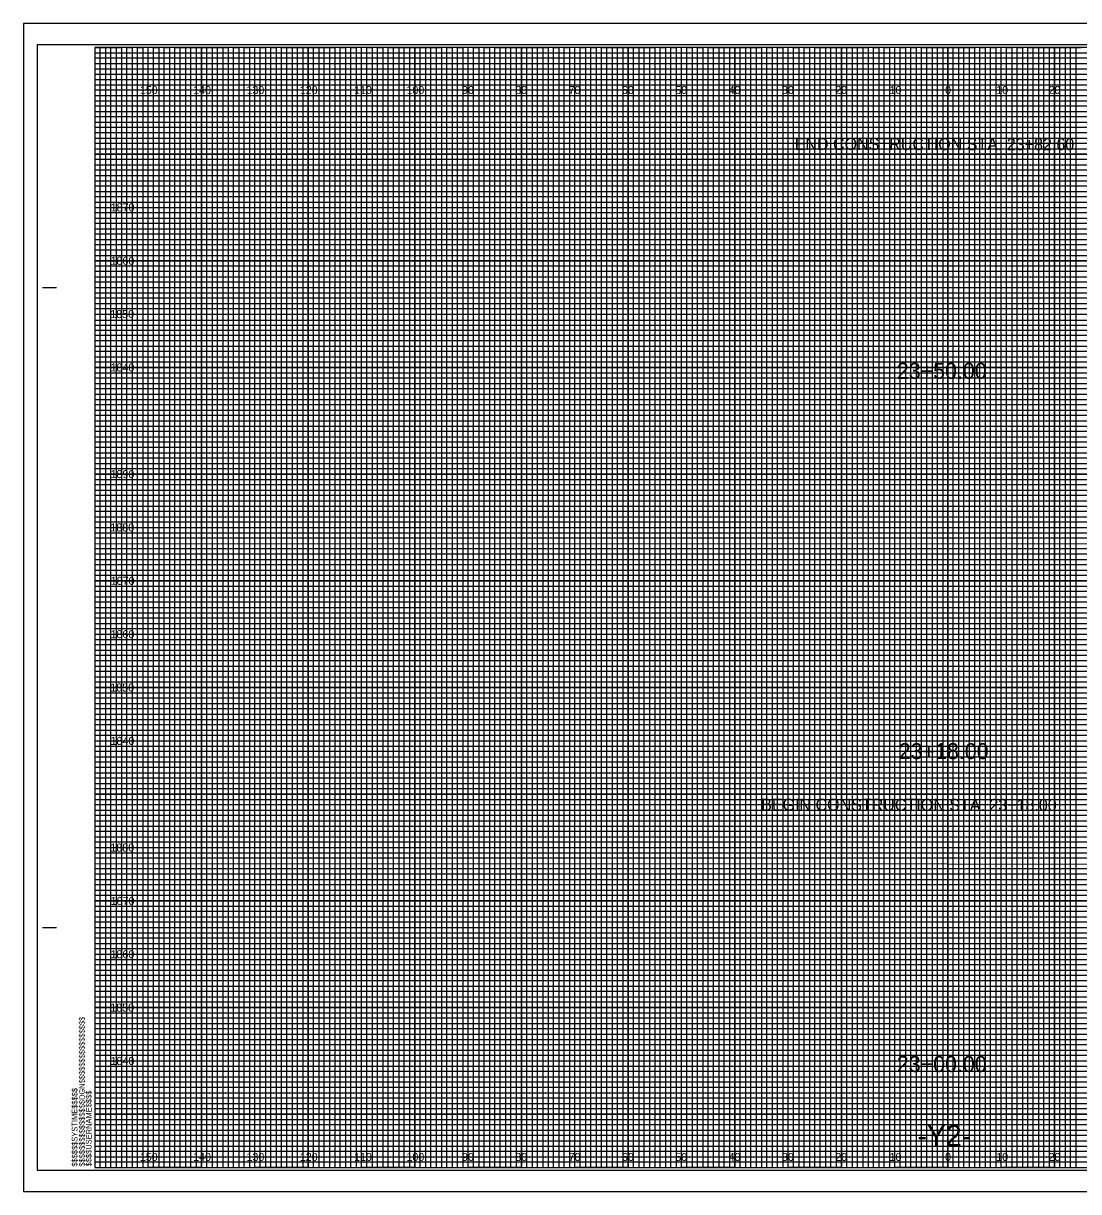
# Model space of a CAD drawing. Extents: x -13 to 323, y -4 to 214.
# Drawn here: x -13.4 to 184.5, y -4.5 to 214.5 of the extents above; entities that cross this region are included whole.
import ezdxf

# ---------------------------------------------------------------- set-up
doc = ezdxf.new("R2010")
doc.units = 0
for name, color, linetype in [('Prop XS Alignment Label', 7, 'Continuous'), ('Prop XS Elevation Labels', 7, 'Continuous'), ('Prop XS Offset Labels', 7, 'Continuous'), ('Prop XS SE Text', 7, 'Continuous'), ('Prop XS Station Labels', 7, 'Continuous'), ('Sheet Cross Section CELL', 7, 'Continuous'), ('Sheet Cross Section Grid Major CELL', 7, 'Continuous'), ('Sheet Cross Section Grid Middle CELL', 7, 'Continuous'), ('Sheet Cross Section Grid Minor 1 CELL', 7, 'Continuous'), ('Sheet Cross Section Grid Minor 2 CELL', 7, 'Continuous'), ('Sheet Cutting Line CELL', 7, 'Continuous'), ('Sheet DOT Grid CELL', 7, 'Continuous'), ('Sheet Plot Border Inside CELL', 7, 'Continuous'), ('Sheet Plot Border Outside CELL', 7, 'Continuous')]:
    doc.layers.add(name, color=color, linetype=linetype)

msp = doc.modelspace()

# ---------------------------------------------------------------- linework, layer by layer
at = {"layer": 'Sheet Cross Section CELL'}
for p, q in [((-9.8, 165), (-7.3, 165)), ((-9.7, 165), (-7.2, 165)), ((-9.8, 45), (-7.3, 45)), ((-9.7, 45), (-7.2, 45))]:
    msp.add_line(p, q, dxfattribs=at)
msp.add_lwpolyline([(320, 210), (0, 210), (0, 0), (320, 0)], close=True, dxfattribs=at)
at = {"layer": 'Sheet Cross Section Grid Major CELL'}
for p, q in [((10, 210), (0, 210)), ((10, 0), (10, 210)), ((30, 210), (20, 210)), ((20, 210), (20, 0)), ((30, 0), (30, 210)), ((50, 210), (40, 210)), ((40, 210), (40, 0)), ((50, 0), (50, 210)), ((70, 210), (60, 210)), ((60, 210), (60, 0)), ((70, 0), (70, 210)), ((90, 210), (80, 210)), ((80, 210), (80, 0)), ((90, 0), (90, 210)), ((110, 210), (100, 210)), ((100, 210), (100, 0)), ((110, 0), (110, 210)), ((130, 210), (120, 210)), ((120, 210), (120, 0)), ((130, 0), (130, 210)), ((150, 210), (140, 210)), ((140, 210), (140, 0)), ((150, 0), (150, 210)), ((170, 210), (160, 210)), ((160, 210), (160, 0)), ((170, 0), (170, 210)), ((190, 210), (180, 210)), ((180, 210), (180, 0)), ((20, 0), (10, 0)), ((40, 0), (30, 0)), ((60, 0), (50, 0)), ((80, 0), (70, 0)), ((100, 0), (90, 0)), ((120, 0), (110, 0)), ((140, 0), (130, 0)), ((160, 0), (150, 0)), ((180, 0), (170, 0))]:
    msp.add_line(p, q, dxfattribs=at)
for points in [[(0, 200), (320, 200), (320, 190), (0, 190)], [(0, 180), (320, 180), (320, 170), (0, 170)], [(0, 160), (320, 160), (320, 150), (0, 150)], [(0, 140), (320, 140), (320, 130), (0, 130)], [(0, 120), (320, 120), (320, 110), (0, 110)], [(0, 100), (320, 100), (320, 90), (0, 90)], [(0, 80), (320, 80), (320, 70), (0, 70)], [(0, 60), (320, 60), (320, 50), (0, 50)], [(0, 40), (320, 40), (320, 30), (0, 30)], [(0, 20), (320, 20), (320, 10), (0, 10)]]:
    msp.add_lwpolyline(points, dxfattribs=at)
at = {"layer": 'Sheet Cross Section Grid Middle CELL'}
for points in [[(0, 210), (5, 210), (5, 0), (15, 0), (15, 210), (25, 210), (25, 0), (35, 0), (35, 210), (45, 210), (45, 0), (55, 0), (55, 210), (65, 210), (65, 0), (75, 0), (75, 210), (85, 210), (85, 0), (95, 0), (95, 210), (105, 210), (105, 0), (115, 0), (115, 210), (125, 210), (125, 0), (135, 0), (135, 210), (145, 210), (145, 0), (155, 0), (155, 210), (165, 210), (165, 0), (175, 0), (175, 210), (185, 210)], [(0, 205), (275, 205)], [(0, 185), (320, 185), (320, 195), (0, 195)], [(0, 165), (320, 165), (320, 175), (0, 175)], [(0, 145), (320, 145), (320, 155), (0, 155)], [(0, 125), (320, 125), (320, 135), (0, 135)], [(0, 105), (320, 105), (320, 115), (0, 115)], [(0, 85), (320, 85), (320, 95), (0, 95)], [(0, 65), (320, 65), (320, 75), (0, 75)], [(0, 45), (320, 45), (320, 55), (0, 55)], [(0, 25), (320, 25), (320, 35), (0, 35)], [(0, 5), (320, 5), (320, 15), (0, 15)]]:
    msp.add_lwpolyline(points, dxfattribs=at)
at = {"layer": 'Sheet Cross Section Grid Minor 1 CELL'}
for p, q in [((0, 209), (260, 209)), ((260, 207.98), (0, 207.98)), ((0, 207.98), (0, 207)), ((0, 207), (260, 207)), ((260, 205.89), (0, 205.89)), ((0, 205.89), (0, 204)), ((0, 204), (320, 204))]:
    msp.add_line(p, q, dxfattribs=at)
for points in [[(0, 203), (270, 203), (320, 203), (320, 202), (0, 202)], [(0, 201), (320, 201), (320, 199), (0, 199)], [(0, 198), (320, 198), (320, 197), (0, 196.98)], [(0, 196), (320, 196), (320, 194), (0, 194)], [(0, 193), (320, 193), (320, 192), (0, 192)], [(0, 191), (320, 191), (320, 189), (0, 189)], [(0, 188), (320, 188), (320, 187), (0, 187)], [(0, 186), (320, 186), (320, 184), (0, 184)], [(0, 183), (320, 183), (320, 182), (0, 182)], [(0, 181), (320, 181), (320, 179), (0, 179)], [(0, 178), (320, 178), (320, 177), (0, 177)], [(0, 176), (320, 176), (320, 173.95), (320, 173), (320, 172), (0, 172)], [(0, 174), (320, 174), (320, 173), (0, 173)], [(0, 171), (320, 171), (320, 169), (0, 169.03)], [(0, 169.03), (320, 169), (320, 168), (0, 168)], [(0, 167), (320, 167), (320, 166), (0, 166)], [(0, 164), (320, 164), (320, 163), (0, 163)], [(0, 162), (320, 162), (320, 161), (0, 161)], [(-0.07, 158.89), (320, 158.89), (320, 157.88), (-0.07, 157.88)], [(0, 157), (320, 157), (320, 156), (0, 156)], [(0, 154), (320, 154), (320, 153), (0, 153)], [(0, 152), (320, 152), (320, 151), (0, 151)], [(0, 149), (320, 149), (320, 148), (0, 148)], [(0, 147), (320, 147), (320, 146), (0, 146)], [(0, 144), (320, 144), (320, 143), (0, 143)], [(0, 142), (320, 142), (320, 141), (0, 141)], [(0, 139), (320, 139), (319.99, 137.98), (0, 138)], [(0, 137), (320, 137), (320, 136), (0, 136)], [(0, 134), (320, 134), (320, 133), (0, 133)], [(0, 132), (320, 132), (320, 131), (0, 131)], [(0, 129), (320, 129), (320, 128), (0, 128)], [(0, 127), (320, 127), (320, 126), (0, 126)], [(0, 124), (320, 124), (320, 123), (0, 123)], [(0, 122), (320, 122), (320, 121), (0, 121)], [(0, 119), (320, 119), (320, 118), (0, 118)], [(0, 116.99), (320.07, 116.91), (320, 116), (0, 116)], [(0, 114), (320, 114), (320, 113), (0, 113)], [(0, 112), (320, 112), (320, 111), (0, 111)], [(0, 109), (320, 109), (320, 108), (0, 108)], [(0, 107), (320, 107), (320, 106), (0, 106)], [(0, 104), (320, 104), (320, 103), (0, 103)], [(0, 102), (320, 102), (320, 101), (0, 101)], [(0, 99), (320, 99), (320, 98), (0, 98)], [(0, 97), (320, 97), (320, 96), (0, 96)], [(0, 94), (320, 94), (320, 93), (0, 93)], [(0, 92), (320, 92), (320, 91), (0, 91)], [(0, 89), (320, 89), (320, 88), (0, 88)], [(0, 87), (320, 87), (320, 86), (0, 86)], [(0, 84), (320, 84), (320, 83), (0, 83)], [(0, 82), (320, 82), (320, 81), (0, 81)], [(0, 79), (320, 79), (319.99, 77.98), (0, 78)], [(0, 77), (320, 77), (320, 76), (0, 76)], [(0, 74), (320, 74), (320, 73), (0, 73)], [(0, 72), (320, 72), (320, 71), (0, 71)], [(0, 69), (320, 69), (320, 68), (0, 68)], [(0, 67), (320, 67), (320, 66), (0, 66)], [(0, 64), (320, 64), (320, 63), (0, 63)], [(0, 62), (320, 62), (320, 61), (0, 61)], [(0, 59), (320, 59), (320, 58), (0, 58)], [(0, 56.99), (320.07, 56.91), (320, 56), (0, 56)], [(0, 54), (320, 54), (320, 53), (0, 53)], [(0, 52), (320, 52), (320, 51), (0, 51)], [(0, 49), (320, 49), (320, 48), (0, 48)], [(0, 47), (320, 47), (320, 46), (0, 46)], [(0, 44), (320, 44), (320, 43), (0, 43)], [(0, 42), (320, 42), (320, 41), (0, 41)], [(0, 39), (320, 39), (320, 38), (0, 38)], [(0, 37), (320, 37), (320, 36), (0, 36)], [(0, 34), (320, 34), (320, 33), (0, 33)], [(0, 32), (320, 32), (320, 31), (0, 31)], [(0, 29), (320, 29), (320, 28), (0, 28)], [(0, 27), (320, 27), (320, 26), (0, 26)], [(0, 24), (320, 24), (320, 23), (0, 23)], [(0, 22), (320, 22), (320, 21), (0, 21)], [(0, 19), (320, 19), (320, 18), (0, 18)], [(0, 17), (320, 17), (320, 16), (0, 16)], [(0, 14), (320, 14), (320, 13), (0, 13)], [(0, 12), (320, 12), (320, 11), (0, 11)], [(0, 9), (320, 9), (320, 8), (0, 8)], [(0, 7), (320, 7), (320, 6), (0, 6)], [(0, 4), (320, 4), (320, 3), (0, 3)], [(0, 2), (320, 2), (320, 1), (0, 1)]]:
    msp.add_lwpolyline(points, dxfattribs=at)
at = {"layer": 'Sheet Cross Section Grid Minor 2 CELL'}
for points in [[(0, 0), (1, 0), (1, 210), (2, 210), (2, 0)], [(2, 0), (3, 0), (3, 210), (4, 210), (4, 0)], [(5, 0), (6, 0), (6, 210), (7, 210), (7, 0)], [(7, 0), (8, 0), (8, 210), (9, 210), (9, 0)], [(10, 0), (11, 0), (11, 210), (12, 210), (12, 0)], [(12, 0), (13, 0), (13, 210), (14, 210), (14, 0)], [(15, 0), (16, 0), (16, 210), (17, 210), (17, 0)], [(17, 0), (18, 0), (18, 210), (19, 210), (19, 0)], [(20, 0), (21, 0), (21, 210), (22, 210), (22, 0)], [(22, 0), (23, 0), (23, 210), (24, 210), (24, 0)], [(25, 0), (26, 0), (26, 210), (27, 210), (27, 0)], [(27, 0), (28, 0), (28, 210), (29, 210), (29, 0)], [(30, 0), (31, 0), (31, 210), (32, 210), (32, 0)], [(32, 0), (33, 0), (33, 210), (34, 210), (34, 0)], [(35, 0), (36, 0), (36, 210), (37, 210), (37, 0)], [(37, 0), (38, 0), (38, 210), (39, 210), (39, 0)], [(40, 0), (41, 0), (41, 210), (42, 210), (42, 0)], [(42, 0), (43, 0), (43, 210), (44, 210), (44, 0)], [(45, 0), (46, 0), (46, 210), (47, 210), (47, 0)], [(47, 0), (48, 0), (48, 210), (49, 210), (49, 0)], [(50, 0), (51, 0), (51, 210), (52, 210), (52, 0)], [(52, 0), (53, 0), (53, 210), (54, 210), (54, 0)], [(55, 0), (56, 0), (56, 210), (57, 210), (57, 0)], [(57, 0), (58, 0), (58, 210), (59, 210), (59, 0)], [(60, 0), (61, 0), (61, 210), (62, 210), (62, 0)], [(62, 0), (63, 0), (63, 210), (64, 210), (64, 0)], [(65, 0), (66, 0), (66, 210), (67, 210), (67, 0)], [(67, 0), (68, 0), (68, 210), (69, 210), (69, 0)], [(70, 0), (71, 0), (71, 210), (72, 210), (72, 0)], [(72, 0), (73, 0), (73, 210), (74, 210), (74, 0)], [(75, 0), (76, 0), (76, 210), (77, 210), (77, 0)], [(77, 0), (78, 0), (78, 210), (79, 210), (79, 0)], [(80, 0), (81, 0), (81, 210), (82, 210), (82, 0)], [(82, 0), (83, 0), (83, 210), (84, 210), (84, 0)], [(85, 0), (86, 0), (86, 210), (87, 210), (87, 0)], [(87, 0), (88, 0), (88, 210), (89, 210), (89, 0)], [(90, 0), (91, 0), (91, 210), (92, 210), (92, 0)], [(92, 0), (93, 0), (93, 210), (94, 210), (94, 0)], [(95, 0), (96, 0), (96, 210), (97, 210), (97, 0)], [(97, 0), (98, 0), (98, 210), (99, 210), (99, 0)], [(100, 0), (101, 0), (101, 210), (102, 210), (102, 0)], [(102, 0), (103, 0), (103, 210), (104, 210), (104, 0)], [(105, 0), (106, 0), (106, 210), (107, 210), (107, 0)], [(107, 0), (108, 0), (108, 210), (109, 210), (109, 0)], [(110, 0), (111, 0), (111, 210), (112, 210), (112, 0)], [(112, 0), (113, 0), (113, 210), (114, 210), (114, 0)], [(115, 0), (116, 0), (116, 210), (117, 210), (117, 0)], [(117, 0), (118, 0), (118, 210), (119, 210), (119, 0)], [(120, 0), (121, 0), (121, 210), (122, 210), (122, 0)], [(122, 0), (123, 0), (123, 210), (124, 210), (124, 0)], [(125, 0), (126, 0), (126, 210), (127, 210), (127, 0)], [(127, 0), (128, 0), (128, 210), (129, 210), (129, 0)], [(130, 0), (131, 0), (131, 210), (132, 210), (132, 0)], [(132, 0), (133, 0), (133, 210), (134, 210), (134, 0)], [(135, 0), (136, 0), (136, 210), (137, 210), (137, 0)], [(137, 0), (138, 0), (138, 210), (139, 210), (139, 0)], [(140, 0), (141, 0), (141, 210), (142, 210), (142, 0)], [(142, 0), (143, 0), (143, 210), (144, 210), (144, 0)], [(145, 0), (146, 0), (146, 210), (147, 210), (147, 0)], [(147, 0), (148, 0), (148, 210), (149, 210), (149, 0)], [(150, 0), (151, 0), (151, 210), (152, 210), (152, 0)], [(152, 0), (153, 0), (153, 210), (154, 210), (154, 0)], [(155, 0), (156, 0), (156, 210), (157, 210), (157, 0)], [(157, 0), (158, 0), (158, 210), (159, 210), (159, 0)], [(160, 0), (161, 0), (161, 210), (162, 210), (162, 0)], [(162, 0), (163, 0), (163, 210), (164, 210), (164, 0)], [(165, 0), (166, 0), (166, 210), (167, 210), (167, 0)], [(167, 0), (168, 0), (168, 210), (169, 210), (169, 0)], [(170, 0), (171, 0), (171, 210), (172, 210), (172, 0)], [(172, 0), (173, 0), (173, 210), (174, 210), (174, 0)], [(175, 0), (176, 0), (176, 210), (177, 210), (177, 0)], [(177, 0), (178, 0), (178, 210), (179, 210), (179, 0)], [(180, 0), (181, 0), (181, 210), (182, 210), (182, 0)], [(182, 0), (183, 0), (183, 210), (184, 210), (184, 0)]]:
    msp.add_lwpolyline(points, dxfattribs=at)
at = {"layer": 'Sheet Cutting Line CELL'}
for p, q in [((323.3, 214.5), (-13.4, 214.5)), ((-13.4, 214.5), (-13.4, -4.5)), ((-13.4, -4.5), (323.3, -4.5))]:
    msp.add_line(p, q, dxfattribs=at)
at = {"layer": 'Sheet DOT Grid CELL'}
for p, q in [((10, 0), (10, 210)), ((20, 0), (20, 210)), ((30, 0), (30, 210)), ((40, 0), (40, 210)), ((50, 0), (50, 210)), ((60, 0), (60, 210)), ((70, 0), (70, 210)), ((80, 0), (80, 210)), ((90, 0), (90, 210)), ((100, 0), (100, 210)), ((110, 0), (110, 210)), ((120, 0), (120, 210)), ((130, 0), (130, 210)), ((140, 0), (140, 210)), ((150, 0), (150, 210)), ((160, 0), (160, 210)), ((170, 0), (170, 210)), ((180, 0), (180, 210)), ((0, 200), (320, 200)), ((0, 190), (320, 190)), ((0, 180), (320, 180)), ((0, 170), (320, 170)), ((0, 160), (320, 160)), ((0, 150), (320, 150)), ((0, 140), (320, 140)), ((0, 130), (320, 130)), ((0, 120), (320, 120)), ((0, 110), (320, 110)), ((0, 100), (320, 100)), ((0, 90), (320, 90)), ((0, 80), (320, 80)), ((0, 70), (320, 70)), ((0, 60), (320, 60)), ((0, 50), (320, 50)), ((0, 40), (320, 40)), ((0, 30), (320, 30)), ((0, 20), (320, 20)), ((0, 10), (320, 10))]:
    msp.add_line(p, q, dxfattribs=at)
at = {"layer": 'Sheet Plot Border Inside CELL'}
msp.add_lwpolyline([(-10.8, -0.5), (322.4, -0.5), (322.4, 210.5), (-10.8, 210.5)], close=True, dxfattribs=at)
at = {"layer": 'Sheet Plot Border Outside CELL'}
msp.add_lwpolyline([(-13.4, -4.5), (323.3, -4.5), (323.3, 214.5), (-13.4, 214.5)], close=True, dxfattribs=at)

# ---------------------------------------------------------------- texts
at = {"layer": 'Prop XS Alignment Label'}
msp.add_text('-Y2-', height=4, dxfattribs=at).set_placement((154.25, 4))
at = {"layer": 'Prop XS Elevation Labels'}
for s, p in [('1870', (2.98, 179.25)), ('1860', (2.95, 169.25)), ('1850', (2.9, 159.25)), ('1840', (2.95, 149.25)), ('1890', (2.95, 129.25)), ('1880', (2.92, 119.25)), ('1870', (2.98, 109.25)), ('1860', (2.95, 99.25)), ('1850', (2.9, 89.25)), ('1840', (2.95, 79.25)), ('1880', (2.92, 59.25)), ('1870', (2.98, 49.25)), ('1860', (2.95, 39.25)), ('1850', (2.9, 29.25)), ('1840', (2.95, 19.25))]:
    msp.add_text(s, height=1.5, dxfattribs=at).set_placement(p)
at = {"layer": 'Prop XS Offset Labels'}
for s, p in [('150', (8.44, 201.25)), ('140', (18.44, 201.25)), ('130', (28.44, 201.25)), ('120', (38.44, 201.25)), ('110', (48.62, 201.25)), ('100', (58.44, 201.25)), ('90', (68.86, 201.25)), ('80', (78.86, 201.25)), ('70', (88.86, 201.25)), ('60', (98.86, 201.25)), ('50', (108.86, 201.25)), ('40', (118.86, 201.25)), ('30', (128.86, 201.25)), ('20', (138.86, 201.25)), ('10', (149.04, 201.25)), ('0', (159.45, 201.25)), ('0', (159.45, 201.25)), ('10', (169.04, 201.25)), ('20', (178.86, 201.25)), ('150', (8.44, 1.25)), ('140', (18.44, 1.25)), ('130', (28.44, 1.25)), ('120', (38.44, 1.25)), ('110', (48.62, 1.25)), ('100', (58.44, 1.25)), ('90', (68.86, 1.25)), ('80', (78.86, 1.25)), ('70', (88.86, 1.25)), ('60', (98.86, 1.25)), ('50', (108.86, 1.25)), ('40', (118.86, 1.25)), ('30', (128.86, 1.25)), ('20', (138.86, 1.25)), ('10', (149.04, 1.25)), ('0', (159.45, 1.25)), ('0', (159.45, 1.25)), ('10', (169.04, 1.25)), ('20', (178.86, 1.25))]:
    msp.add_text(s, height=1.5, dxfattribs=at).set_placement(p)
at = {"layer": 'Prop XS SE Text'}
for s, p in [('END CONSTRUCTION STA. 23+82.60', (131.25, 190.78)), ('BEGIN CONSTRUCTION STA. 23+18.00', (124.96, 66.93))]:
    msp.add_text(s, height=2.25, rotation=359.9227, dxfattribs=at).set_placement(p)
at = {"layer": 'Prop XS Station Labels'}
for s, p in [('23+50.00', (150.41, 147.86)), ('23+18.00', (150.77, 76.57)), ('23+00.00', (150.41, 17.92))]:
    msp.add_text(s, height=3, dxfattribs=at).set_placement(p)
at = {"layer": 'Sheet Cross Section CELL'}
for s, p in [('$$$$$$$$$$$$$$$$DGN$$$$$$$$$$$$$$$$', (-1.88, 0.18)), ('$$$$$$SYSTIME$$$$$', (-3.26, 0.18)), ('$$$$USERNAME$$$$', (-0.62, 0.23))]:
    msp.add_text(s, height=1.05, rotation=90, dxfattribs=at).set_placement(p)

doc.saveas('drawing.dxf')
